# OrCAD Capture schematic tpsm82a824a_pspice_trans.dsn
size D; title: TPSM82A824A: High-Efficiency, Step-Down Converter Module; rev: 1.0; note: Datasheet: SLVSKL6     EVM: SLVUDO6; note: Synchronous Step Down Converter
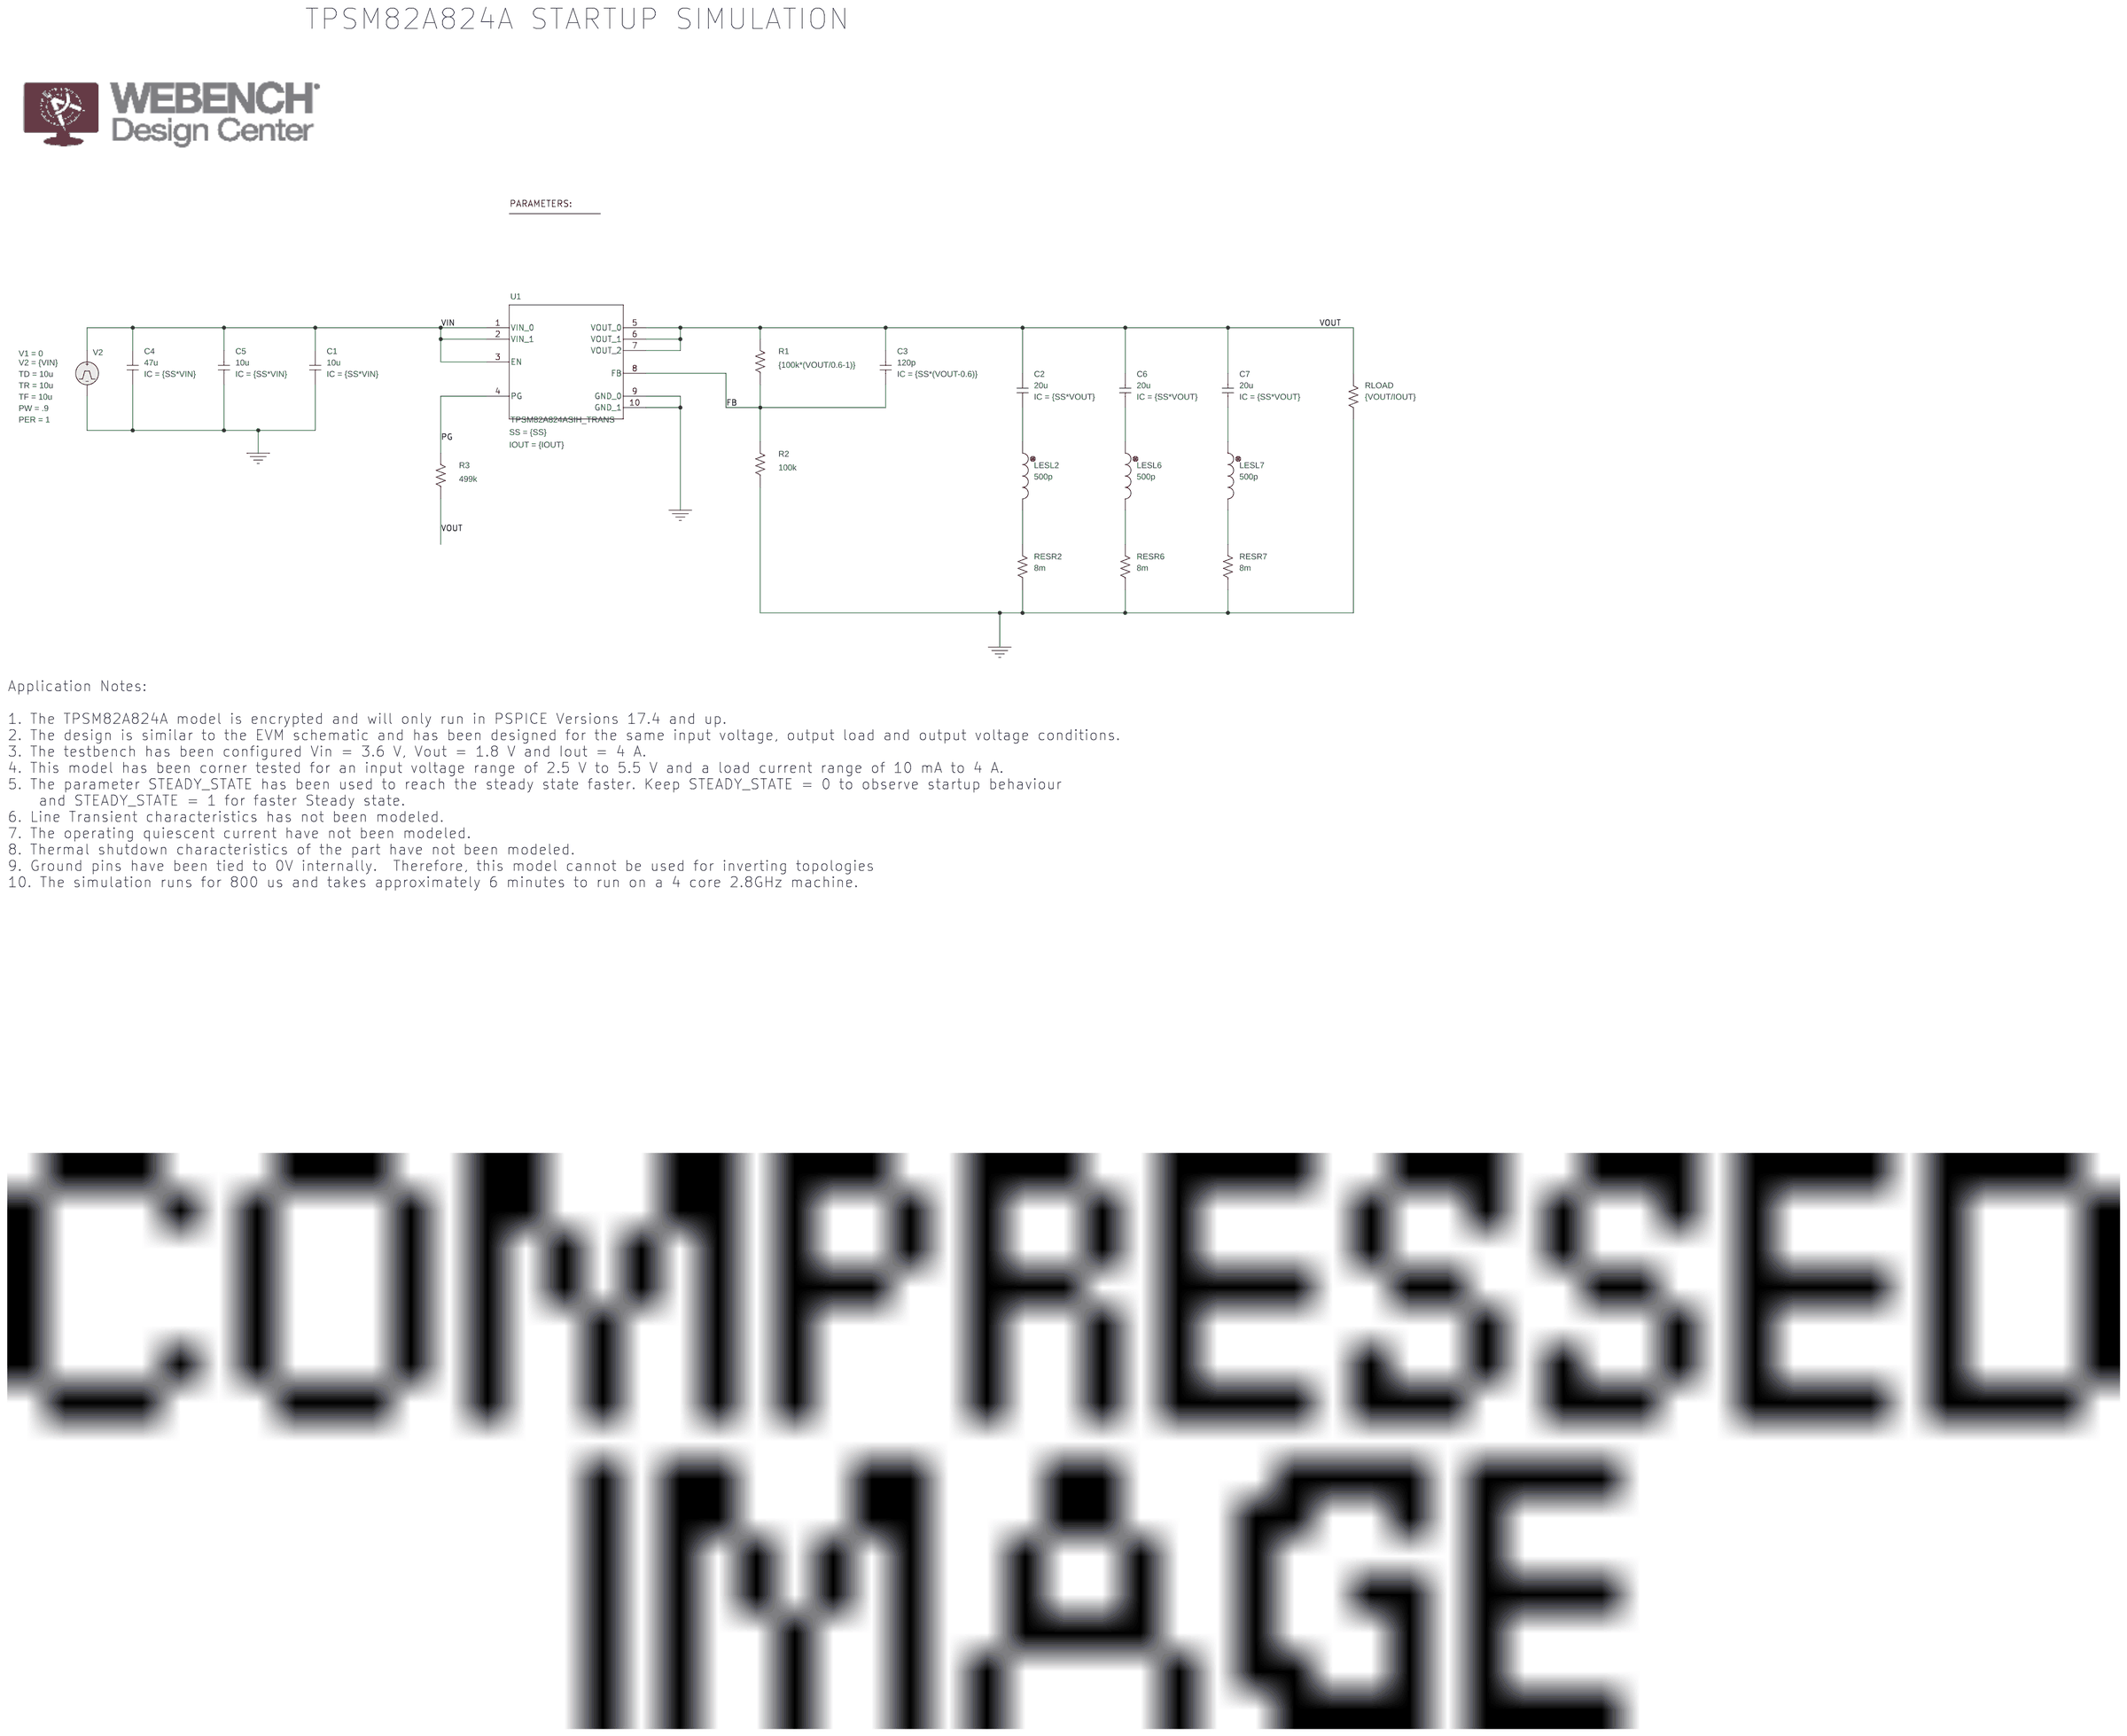
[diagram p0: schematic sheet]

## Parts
1  PARAM
C1  10u  [cap196]
C2  20u  [cap196]
C3  120p  [cap196]
C4  47u  [cap196]
C5  10u  [cap196]
C6  20u  [cap196]
C7  20u  [cap196]
LESL2  500p  [DISC/.350x.175/LS.200x.100/.034]
LESL6  500p  [DISC/.350x.175/LS.200x.100/.034]
LESL7  500p  [DISC/.350x.175/LS.200x.100/.034]
R1  {100k*(VOUT/0.6-1)}  [AX/RC05]
R2  100k  [AX/RC05]
R3  499k  [AX/RC05]
RESR2  8m  [AX/RC05]
RESR6  8m  [AX/RC05]
RESR7  8m  [AX/RC05]
RLOAD  {VOUT/IOUT}  [AXRC05]
U1  TPSM82A824ASIH_TRANS  [SIL0010D-MFG]
V2  VPULSE

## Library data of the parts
1 = PARAM: IOUT: 4; SS: 0; VIN: 3.6; VOUT: 1.8
C1 C4 C5 = C: IC: {SS*VIN}
C2 C6 C7 = C: IC: {SS*VOUT}
C3 = C: IC: {SS*(VOUT-0.6)}
LESL2 LESL6 LESL7 = L
R1-R3 RESR2 RESR6 RESR7 RLOAD = R
U1 = TPSM82A824ASIH_TRANS: IOUT: {IOUT}; SS: {SS}
V2 = VPULSE: PER: 1; PW: .9; TD: 10u; TF: 10u; TR: 10u; V1: 0; V2: {VIN}

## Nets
VIN: C1.1 C4.1 C5.1 U1.1(VIN_0) U1.2(VIN_1) U1.3(EN) V2.1(+)
0: C1.2 C4.2 C5.2 R2.1 RESR2.1 RESR6.1 RESR7.1 RLOAD.2 U1.9(GND_0) U1.10(GND_1) V2.2(-)
FB: C3.2 R1.1 R2.2 U1.8(FB)
PG: R3.2 U1.4(PG)
VOUT: C2.1 C3.1 C6.1 C7.1 R1.2 R3.1 RLOAD.1 U1.5(VOUT_0) U1.6(VOUT_1) U1.7(VOUT_2)
N16770285: C2.2 LESL2.1
N16770289: C6.2 LESL6.1
N16770297: C7.2 LESL7.1
N16770473: LESL2.2 RESR2.2
N16770477: LESL6.2 RESR6.2
N16770483: LESL7.2 RESR7.2

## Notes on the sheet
- TPSM82A824A STARTUP SIMULATION
- Application Notes:
  1. The TPSM82A824A model is encrypted and will only run in PSPICE Versions 17.4 and up.
  2. The design is similar to the EVM schematic and has been designed for the same input voltage, output load and output voltage conditions.
  3. The testbench has been configured Vin = 3.6 V, Vout = 1.8 V and Iout = 4 A.
  4. This model has been corner tested for an input voltage range of 2.5 V to 5.5 V and a load current range of 10 mA to 4 A.
  5. The parameter STEADY_STATE has been used to reach the steady state faster. Keep STEADY_STATE = 0 to observe startup behaviour
      and STEADY_STATE = 1 for faster Steady state.
  6. Line Transient characteristics has not been modeled.
  7. The operating quiescent current have not been modeled.
  8. Thermal shutdown characteristics of the part have not been modeled.
  9. Ground pins have been tied to 0V internally.  Therefore, this model cannot be used for inverting topologies
  10. The simulation runs for 800 us and takes approximately 6 minutes to run on a 4 core 2.8GHz machine.
